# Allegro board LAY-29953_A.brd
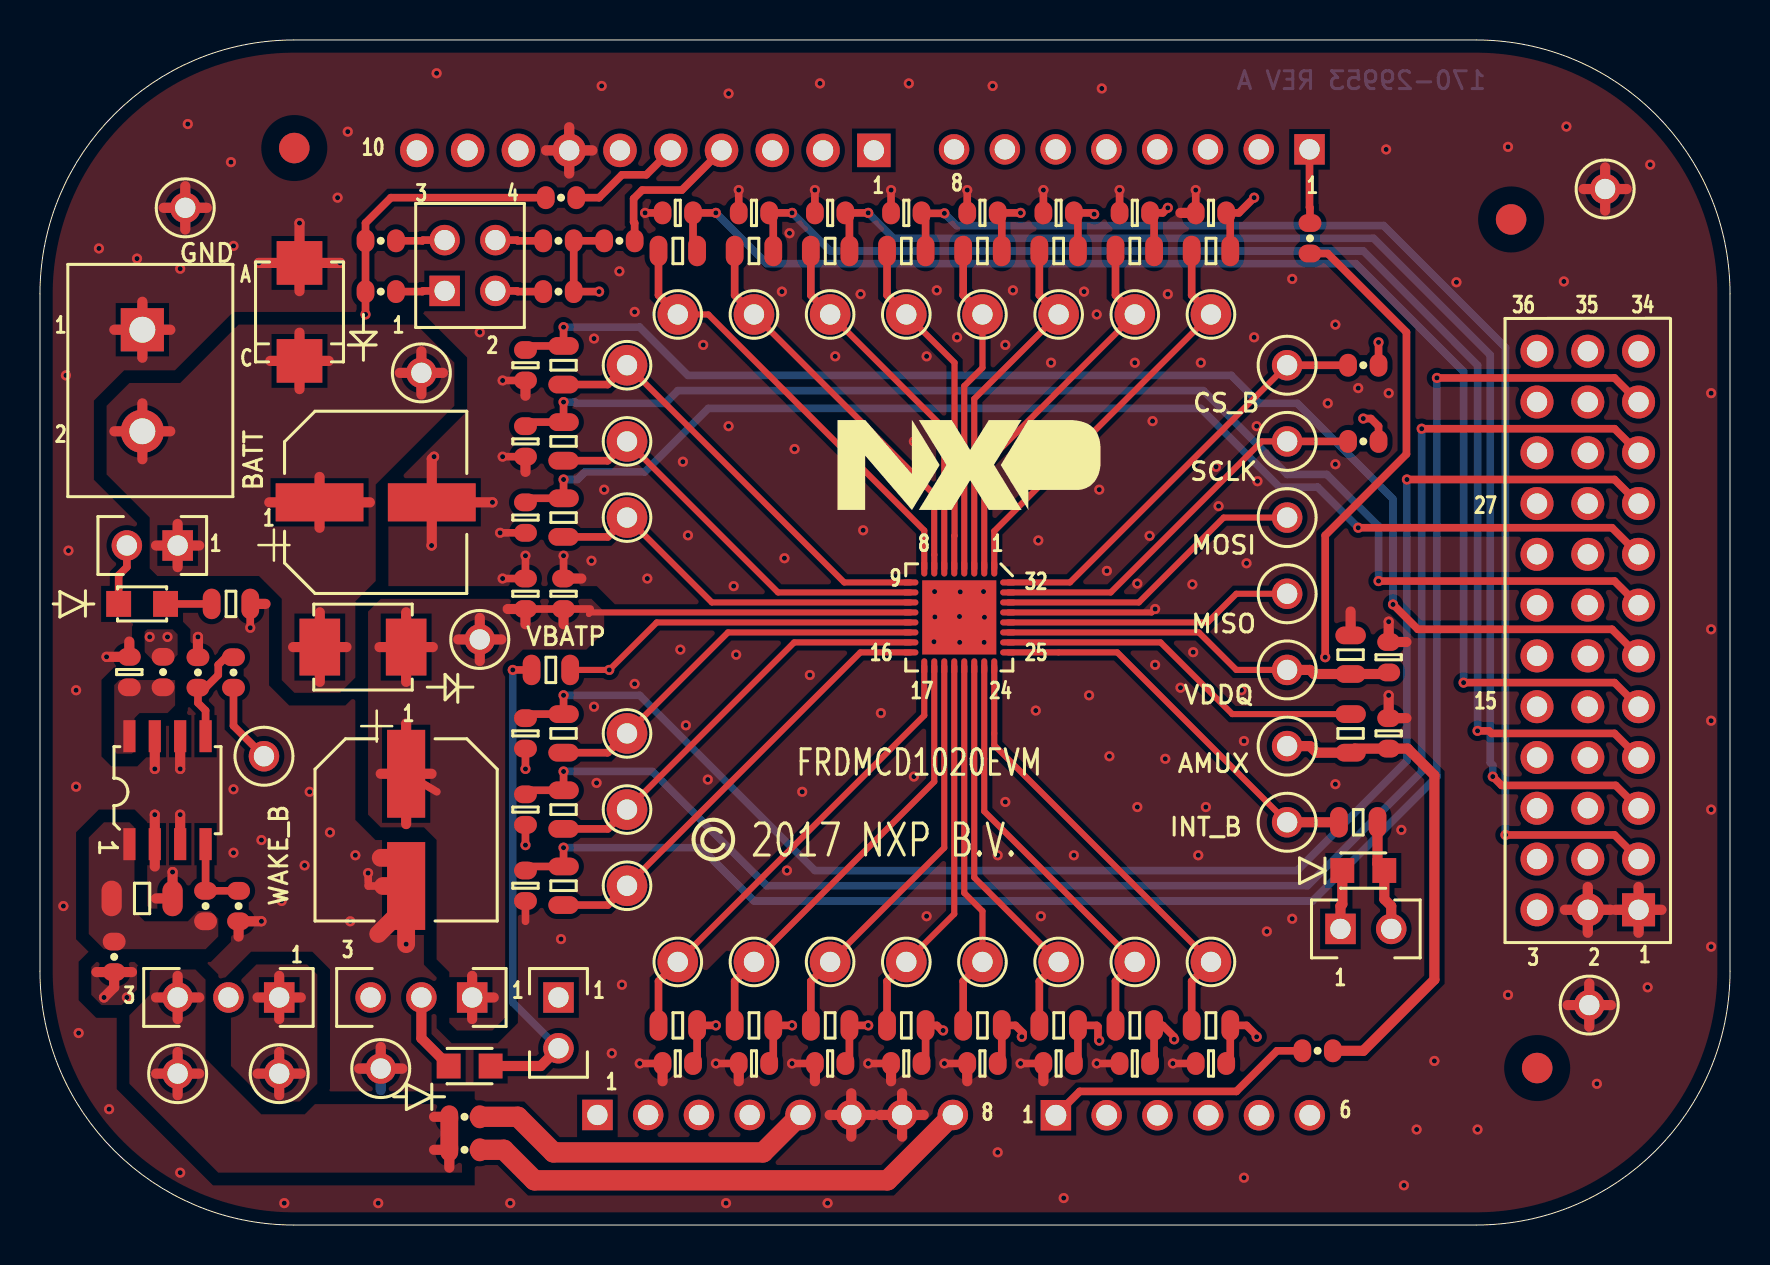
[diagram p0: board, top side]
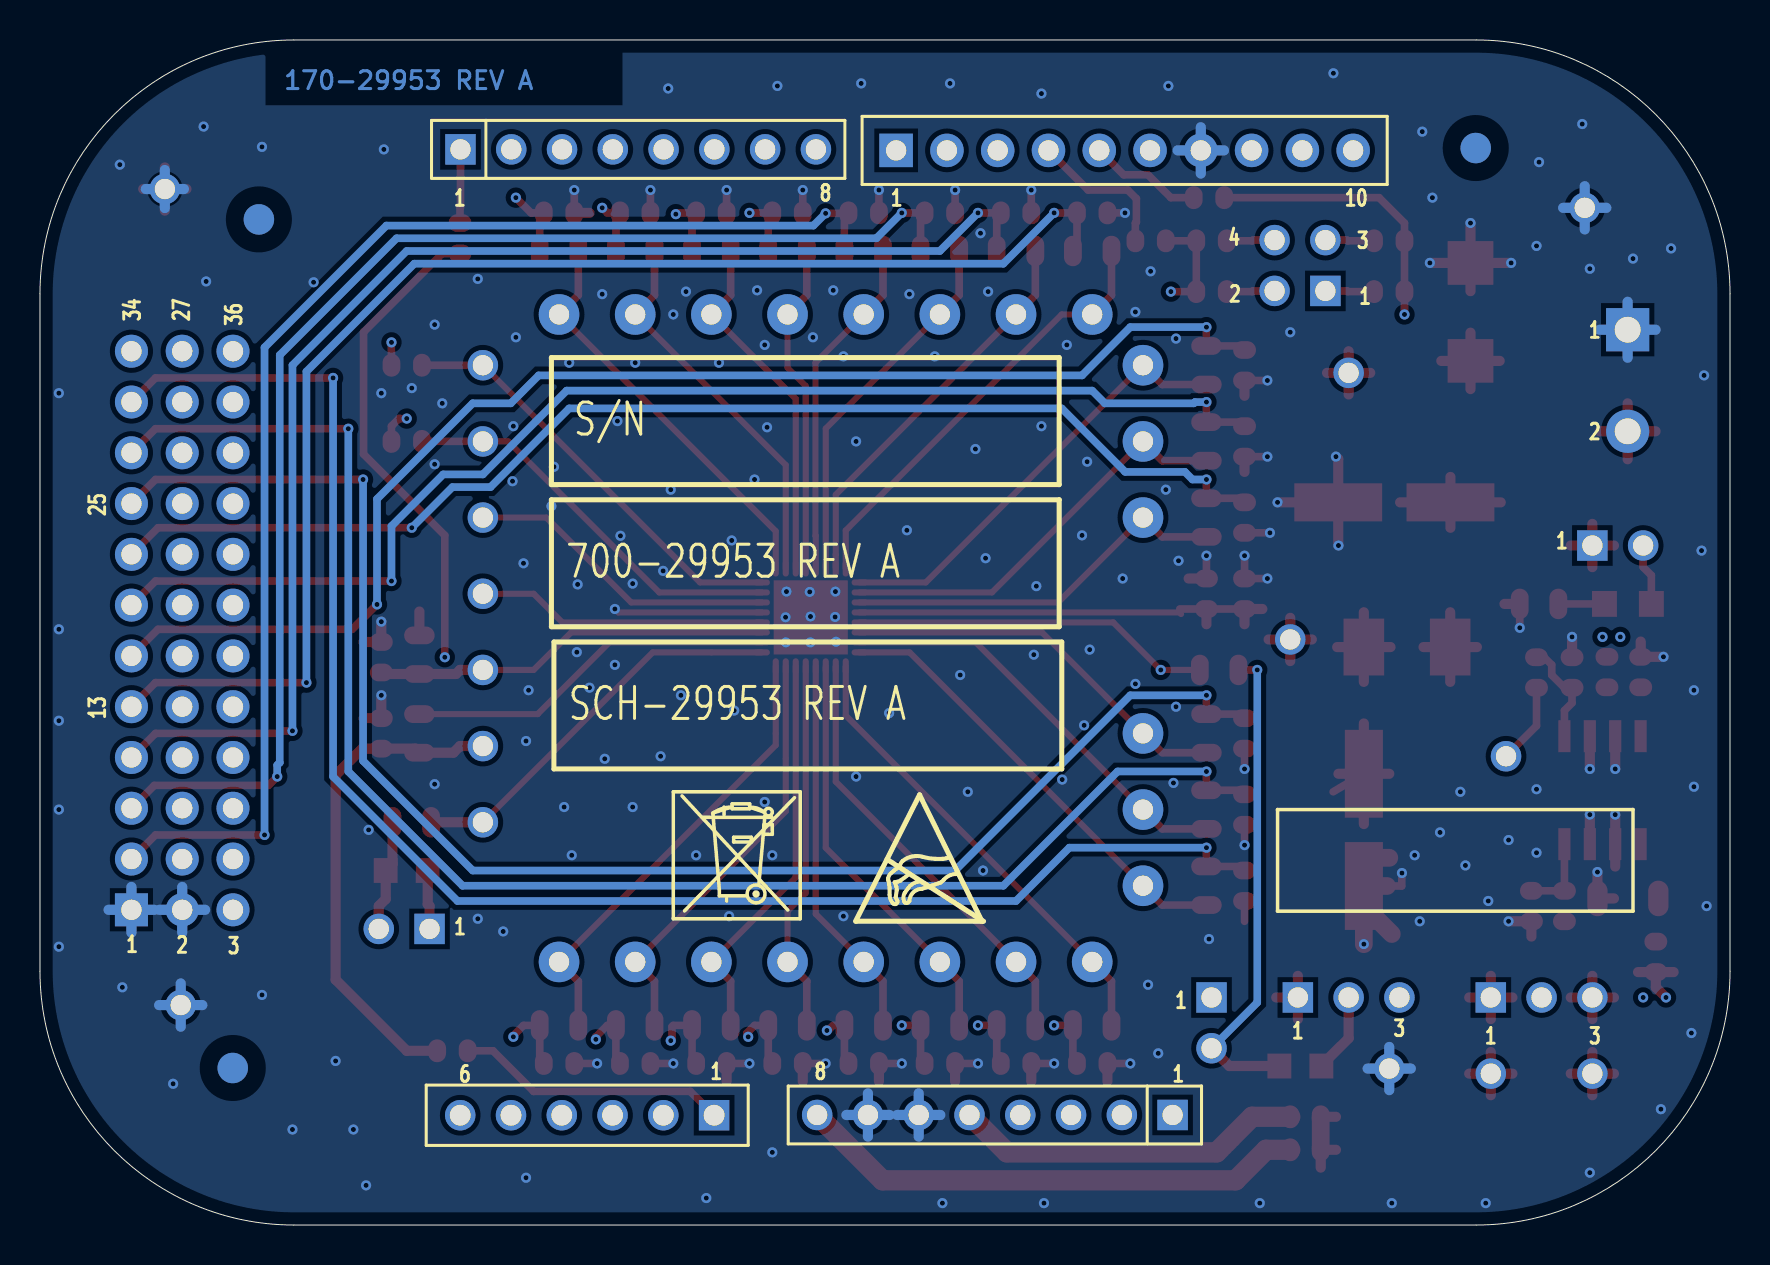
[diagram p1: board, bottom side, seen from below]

Outline 84.54 x 59.27 mm; copper layers: TOP, INNER_1, INNER_2, BOTTOM. Coordinates in mm from the lower left corner of the outline.
Outline path: 0,46.57 arc(3.72,55.55) 12.7,59.27 71.84,59.27 arc(80.82,55.55) 84.54,46.57 84.54,12.7 arc(80.82,3.72) 71.84,0 12.7,0 arc(3.72,3.72) 0,12.7 0,46.57

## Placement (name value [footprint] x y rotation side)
BATT1  TEST POINT RED  [TEST_LOOP]  19.08 42.62 0 top
C1  0.1uF  [CC0603_OV]  43.33 50.62 180 top
C2  0.1uF  [CC0603_OV]  39.52 50.62 180 top
C3  0.1uF  [CC0603_OV]  35.71 50.62 180 top
C4  0.1uF  [CC0603_OV]  31.9 50.62 180 top
C5  0.1uF  [CC0603_OV]  24.28 43 270 top
C6  0.1uF  [CC0603_OV]  24.28 39.19 270 top
C7  0.1uF  [CC0603_OV]  24.28 35.38 270 top
C8  0.1uF  [CC0603_OV]  24.28 24.59 270 top
C9  0.1uF  [CC0603_OV]  24.28 20.78 270 top
C10  0.1uF  [CC0603_OV]  24.28 16.97 270 top
C11  0.1uF  [CC0603_OV]  31.9 8.08 180 top
C12  0.1uF  [CC0603_OV]  35.71 8.08 180 top
C13  0.1uF  [CC0603_OV]  39.52 8.08 180 top
C14  0.1uF  [CC0603_OV]  43.33 8.08 180 top
C22  100uF  [CCE8P3X8P3]  18.32 19.76 270 top
C23  1000PF  [CC0603_OV]  67.46 24.59 90 top
C24  0.1uF  [CC0603_OV]  26.19 31.57 90 top
C25  1000PF  [CC0603_OV]  24.28 31.57 90 top
C26  0.1uF  [CC0603_OV]  67.46 28.4 90 top
C31  0.1uF  [CC0603_OV]  58.57 8.08 180 top
C32  0.1uF  [CC0603_OV]  54.76 8.08 180 top
C33  0.1uF  [CC0603_OV]  50.95 8.08 180 top
C34  0.1uF  [CC0603_OV]  47.14 8.08 180 top
C35  0.1uF  [CC0603_OV]  47.14 50.62 180 top
C36  0.1uF  [CC0603_OV]  50.95 50.62 180 top
C37  0.1uF  [CC0603_OV]  54.76 50.62 180 top
C38  0.1uF  [CC0603_OV]  58.57 50.62 180 top
C39  0.1UF  [CC0603_OV]  4.47 27.66 90 top
C40  10uF  [CC1206_OV]  5.11 16.33 0 top
C41  10uF  [CC0805_OV]  65.56 28.53 90 top
C42  100uF  [CCE8P3X8P3]  16.79 36.15 0 top
D1  ES3AB-13-F  [SMB_4P57X3P94MM]  16.16 28.91 180 top
D2  RED  [LED_2P_0805]  21.49 7.95 180 top
D3  RED  [LED_2P_0805]  66.19 17.73 180 top
D4  SMBJ40  [DO-214AA_A]  12.98 45.67 90 top
D5  GREEN  [LED2_2P34_2P1X1P25]  5.11 31.07 180 top
GND1  TEST POINT BLACK  [TEST_LOOP]  7.27 50.88 0 top
GND2  TEST POINT BLACK  [TEST_LOOP]  17.05 7.83 0 top
GND3  TEST POINT BLACK  [TEST_LOOP]  78.29 51.82 0 top
GND4  TEST POINT BLACK  [TEST_LOOP]  77.5 11 0 top
J1  HDR 1X10  [HDR110]  41.71 53.75 90 bottom
J2  HDR_1X8  [JUMP1X8-6040]  63.51 53.8 90 bottom
J3  HDR 1X2  [HDR102]  65.05 14.81 90 top
J4  HDR 1X2  [HDR102]  6.89 33.99 270 top
J5  OSTTC022162  [CON2_TB_5P08_TH_OSTTC]  5.12 44.78 270 top
J6  HDR_1X3  [HDR103]  21.62 11.38 270 top
J7  HDR 1X2  [HDR102]  25.94 11.38 0 top
J8  HDR_1X8  [JUMP1X8-6040]  27.88 5.5 270 bottom
J9  HDR 1X6  [HDR106_TH_TSW]  50.82 5.49 270 bottom
J14  HDR_1X3  [HDR103]  11.97 11.38 270 top
J16  HDR_3X12  [HDR_3X12_100_TH]  79.96 15.77 90 top
J17  SKT_2X2  [SKT2X2_TH_SSQ]  20.24 46.72 180 top
NOREF  -  []  29.13 39.23 90 top
NOREF#2  -  []  43.48 27.89 90 top
NOREF#3  -  []  230.3 -47.15 0 top
NOREF#4  -  []  44.23 27.94 0 top
NOREF#5  -  []  43.48 27.89 90 top
NOREF#6  -  []  33.68 19.26 0 top
NOREF#7  -  []  0 46.57 0 top
NOREF#8  -  []  47.73 27.94 90 top
NOREF#9  -  []  43.53 28.64 0 top
NOREF#10  -  []  -16.61 -33.78 0 top
NOREF#11  -  [unnamed#2]  74.89 7.85 0 top
NOREF#12  -  [unnamed#2]  12.72 53.87 0 top
NOREF#13  -  []  48.48 32.38 90 top
NOREF#14  -  []  47.73 27.94 90 top
NOREF#15  -  []  230.3 -73.82 90 top
NOREF#16  -  []  48.48 27.89 0 top
NOREF#17  -  []  -408.02 -336.95 0 top
NOREF#18  -  []  6.89 7.57 0 top
NOREF#19  -  []  43.53 28.64 0 top
NOREF#20  -  []  20.24 46.72 90 top
NOREF#21  -  []  39.17 53.75 0 top
NOREF#22  -  [unnamed#2]  73.59 50.3 0 top
NOREF#23  -  []  48.48 32.38 90 top
NOREF#24  -  []  43.53 31.64 90 top
NOREF#25  -  []  48.43 28.64 90 top
NOREF#26  -  []  71.84 0 90 top
NOREF#27  -  []  48.43 28.64 90 top
NOREF#28  -  []  4.85 20.78 0 top
NOREF#29  -  []  43.53 31.64 90 top
NOREF#30  -  []  5.04 56.7 0 top
NOREF#31  -  []  44.23 32.84 0 top
NOREF#32  -  []  44.23 27.94 0 top
NOREF#33  -  []  -381.99 188.19 0 top
NOREF#34  -  []  39.91 35.77 0 top
NOREF#35  -  []  43.72 15.19 180 bottom
NOREF#36  -  []  58.83 22.81 180 bottom
NOREF#37  -  [unnamed#2]  12.72 53.87 180 bottom
NOREF#38  -  []  91.8 42.45 180 bottom
NOREF#39  -  []  4.85 20.78 0 bottom
NOREF#40  -  [unnamed#2]  74.9 7.85 180 bottom
NOREF#41  -  []  52.86 15.32 180 bottom
NOREF#42  -  [unnamed#2]  73.59 50.3 180 bottom
NOREF#43  -  []  58.96 29.92 180 bottom
NOREF#44  -  []  33.56 43.39 0 bottom
R1  100  [RC0805_OV]  43.33 48.72 180 top
R2  100  [RC0805_OV]  39.52 48.72 180 top
R3  100  [RC0805_OV]  35.71 48.72 180 top
R4  100  [RC0805_OV]  31.9 48.72 180 top
R5  100  [RC0805_OV]  26.19 43 270 top
R6  100  [RC0805_OV]  26.19 39.19 270 top
R7  100  [RC0805_OV]  26.19 35.38 270 top
R8  100  [RC0805_OV]  26.19 24.59 270 top
R9  100  [RC0805_OV]  26.19 20.78 270 top
R10  100  [RC0805_OV]  26.19 16.97 270 top
R11  100  [RC0805_OV]  31.9 9.98 180 top
R12  100  [RC0805_OV]  35.71 9.98 180 top
R13  100  [RC0805_OV]  39.52 9.98 180 top
R14  100  [RC0805_OV]  43.33 9.98 180 top
R22  1K  [RC0805_OV]  65.56 24.59 90 top
R23  10K  [RC0805_OV]  65.94 20.14 0 top
R24  100  [RC0805_OV]  58.57 48.72 0 top
R25  100  [RC0805_OV]  54.76 48.72 0 top
R26  100  [RC0805_OV]  50.95 48.72 0 top
R27  100  [RC0805_OV]  47.14 48.72 0 top
R28  100  [RC0805_OV]  47.14 9.98 0 top
R29  100  [RC0805_OV]  50.95 9.98 0 top
R30  100  [RC0805_OV]  54.76 9.98 0 top
R31  100  [RC0805_OV]  58.57 9.98 0 top
R36  10K  [RC0805_OV]  25.55 27.76 180 top
R37  0  [RC0603_OV]  66.19 43 0 top
R38  0  [RC0603_OV]  66.19 39.19 0 top
R39  0  [RC0603_OV]  26.06 51.39 0 top
R40  0  [RC0603_OV]  28.98 49.23 0 top
R41  0  [RC0603_OV]  63.53 49.35 90 top
R42  0  [RC0603_OV]  3.71 13.41 270 top
R43  0  [RC0603_OV]  6.16 27.66 270 top
R44  10K  [RC0805_OV]  9.55 31.07 180 top
R45  0  [RC0603_OV]  21.24 5.41 0 top
R46  0  [RC0603_OV]  21.24 3.76 0 top
R47  0  [RC0603_OV]  63.91 8.71 180 top
R48  0  [RC0603_OV]  17.05 46.69 180 top
R49  0  [RC0603_OV]  17.05 49.23 180 top
R50  0  [RC0603_OV]  25.94 46.69 180 top
R51  0  [RC0603_OV]  25.94 49.23 180 top
R61  47K  [RC0603_OV]  8.28 15.95 270 top
R62  150.0K  [RC0603_OV]  9.93 15.95 270 top
R63  0  [RC0603_OV]  7.9 27.64 270 top
R64  0  [RC0603_OV]  9.68 27.64 90 top
SG0  TH  [MST_TESTPOINT]  43.33 45.54 0 top
SG1  TH  [MST_TESTPOINT]  39.52 45.54 0 top
SG2  TH  [MST_TESTPOINT]  35.71 45.54 0 top
SG3  TH  [MST_TESTPOINT]  31.9 45.54 0 top
SG4  TH  [MST_TESTPOINT]  29.36 43 90 top
SG5  TH  [MST_TESTPOINT]  29.36 39.19 90 top
SG6  TH  [MST_TESTPOINT]  29.36 35.38 90 top
SG7  TH  [MST_TESTPOINT]  29.36 24.59 90 top
SG8  TH  [MST_TESTPOINT]  29.36 20.78 90 top
SG9  TH  [MST_TESTPOINT]  29.36 16.97 0 top
SG10  TH  [MST_TESTPOINT]  31.9 13.16 90 top
SG11  TH  [MST_TESTPOINT]  35.71 13.16 90 top
SG12  TH  [MST_TESTPOINT]  39.52 13.16 90 top
SG13  TH  [MST_TESTPOINT]  43.33 13.16 90 top
SP0  TH  [MST_TESTPOINT]  58.57 45.54 90 top
SP1  TH  [MST_TESTPOINT]  54.76 45.54 90 top
SP2  TH  [MST_TESTPOINT]  50.95 45.54 90 top
SP3  TH  [MST_TESTPOINT]  47.14 45.54 90 top
SP4  TH  [MST_TESTPOINT]  47.14 13.16 180 top
SP5  TH  [MST_TESTPOINT]  50.95 13.16 0 top
SP6  TH  [MST_TESTPOINT]  54.76 13.16 0 top
SP7  TH  [MST_TESTPOINT]  58.57 13.16 0 top
TP1  TEST POINT RED  [TEST_LOOP]  22 29.29 0 top
TP2  TEST POINT RED  [TEST_LOOP]  62.38 27.76 0 top
TP3  TEST POINT RED  [TEST_LOOP]  62.38 39.19 0 top
TP4  TEST POINT RED  [TEST_LOOP]  62.38 31.57 0 top
TP5  TEST POINT RED  [TEST_LOOP]  62.38 35.38 0 top
TP6  TEST POINT RED  [TEST_LOOP]  62.38 43 0 top
TP7  TEST POINT RED  [TEST_LOOP]  62.38 20.14 0 top
TP8  TEST POINT RED  [TEST_LOOP]  11.2 23.45 0 top
TP9  TEST POINT RED  [TEST_LOOP]  62.38 23.95 0 top
U2  LM2931CDG  [SO8_1P27_4X5]  6.38 21.75 90 top
U3  PC33CD1020AES  [QFN32_0P5_5X5_S146EP]  45.98 30.39 270 top
UNK3V3  TEST POINT RED  [TEST_LOOP]  11.97 7.57 0 top
UNK5V0  TEST POINT RED  [TEST_LOOP]  6.89 7.57 0 top

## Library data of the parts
BATT1 GND1-GND4 TP1-TP9 UNK3V3 UNK5V0 = TestLoop
C1-C14 C23-C26 C31-C41 = CAP_NP
C22 C42 = CAP_POL
D1 = DIODE
D2 D3 D5 = LED
D4 = DIODE_TVS
J1 = HDR-1X10
J2 J8 = HDR-1X8
J3-J5 J7 = CONN_HDR_2X1
J6 J14 = CONN_HDR_3X1
J9 = CONN_HDR_6X1
J16 = HDR-3X12
J17 = CONN_HDR_2X2
R1-R14 R22-R31 R36-R51 R61-R64 = RES
SG0-SG13 SP0-SP7 = T POINT S
U2 = LM2931_SO8
U3 = PC33978_QFN32

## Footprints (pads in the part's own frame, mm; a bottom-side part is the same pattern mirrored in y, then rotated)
CC0603_OV
  oval 0.889x1.143 smd: 1(-0.762,0) 2(0.762,0)
CC0805_OV
  oval 0.889x1.524 smd: 1(-0.965,0) 2(0.965,0)
CC1206_OV
  oval 1.016x1.778 smd: 1(-1.524,0) 2(1.524,0)
CCE8P3X8P3
  rect 4.394x1.905 smd: 1(-2.807,0) 2(2.807,0)
CON2_TB_5P08_TH_OSTTC
  rect 2.159x2.159 hole 1.295: 1(0,0)
  round 2.159 hole 1.295: 2(5.08,0)
DO-214AA_A
  rect 2.184x2.286 smd: A(2.45,0) C(-2.45,0)
HDR102
  rect 1.524x1.524 hole 1.016: 1(0,0)
  round 1.524 hole 1.016: 2(0,-2.54)
HDR103
  rect 1.524x1.524 hole 1.016: 1(0,0)
  round 1.524 hole 1.016: 2(0,-2.54) 3(0,-5.08)
HDR106_TH_TSW
  rect 1.524x1.524 hole 1.041: 1(0,0)
  round 1.524 hole 1.041: 2(0,-2.54) 3(0,-5.08) 4(0,-7.62) 5(0,-10.16) 6(0,-12.7)
HDR110
  rect 1.676x1.676 hole 1.016: 1(0,0)
  round 1.676 hole 1.016: 2(0,-2.54) 3(0,-5.08) 4(0,-7.62) 5(0,-10.16) 6(0,-12.7) 7(0,-15.24) 8(0,-17.78) 9(0,-20.32) 10(0,-22.86)
HDR_3X12_100_TH
  rect 1.651x1.651 hole 1.016: 1(0,0)
  round 1.651 hole 1.016: 2(0,2.54) 3(0,5.08) 4(2.54,0) 5(2.54,2.54) 6(2.54,5.08) 7(5.08,0) 8(5.08,2.54) 9(5.08,5.08) 10(7.62,0) 11(7.62,2.54) 12(7.62,5.08) 13(10.16,0) 14(10.16,2.54) 15(10.16,5.08) 16(12.7,0) 17(12.7,2.54) 18(12.7,5.08) 19(15.24,0) 20(15.24,2.54) 21(15.24,5.08) 22(17.78,0) 23(17.78,2.54) 24(17.78,5.08) 25(20.32,0) 26(20.32,2.54) 27(20.32,5.08) 28(22.86,0) 29(22.86,2.54) 30(22.86,5.08) 31(25.4,0) 32(25.4,2.54) 33(25.4,5.08) 34(27.94,0) 35(27.94,2.54) 36(27.94,5.08)
JUMP1X8-6040
  rect 1.524x1.524 hole 1.016: 1(0,0)
  round 1.524 hole 1.016: 2(0,-2.54) 3(0,-5.08) 4(0,-7.62) 5(0,-10.16) 6(0,-12.7) 7(0,-15.24) 8(0,-17.78)
LED2_2P34_2P1X1P25
  rect 1.245x1.295 smd: A(1.172,0) C(-1.172,0)
LED_2P_0805
  rect 1.194x1.245 smd: A(1.05,0) C(-1.05,0)
MST_TESTPOINT
  round 2.032 hole 1.016: 1(0,0)
QFN32_0P5_5X5_S146EP
  oval 0.813x0.305 smd: 1(-2.45,1.75) 2(-2.45,1.25) 3(-2.45,0.75) 4(-2.45,0.25) 5(-2.45,-0.25) 6(-2.45,-0.75) 7(-2.45,-1.25) 8(-2.45,-1.75) 17(2.45,-1.75) 18(2.45,-1.25) 19(2.45,-0.75) 20(2.45,-0.25) 21(2.45,0.25) 22(2.45,0.75) 23(2.45,1.25) 24(2.45,1.75)
  oval 0.305x0.813 smd: 9(-1.75,-2.45) 10(-1.25,-2.45) 11(-0.75,-2.45) 12(-0.25,-2.45) 13(0.25,-2.45) 14(0.75,-2.45) 15(1.25,-2.45) 16(1.75,-2.45) 25(1.75,2.45) 26(1.25,2.45) 27(0.75,2.45) 28(0.25,2.45) 29(-0.25,2.45) 30(-0.75,2.45) 31(-1.25,2.45) 32(-1.75,2.45)
  rect 3.708x3.708 smd: 33(0,0)
RC0603_OV
  oval 0.889x1.143 smd: 1(-0.762,0) 2(0.762,0)
RC0805_OV
  oval 0.889x1.524 smd: 1(-0.965,0) 2(0.965,0)
SKT2X2_TH_SSQ
  rect 1.524x1.524 hole 1.016: 1(0,0)
  round 1.524 hole 1.016: 2(-2.54,0) 3(0,-2.54) 4(-2.54,-2.54)
SMB_4P57X3P94MM
  rect 2.032x2.845 smd: A(2.16,0) C(-2.16,0)
SO8_1P27_4X5
  rect 1.6x0.61 smd: 1(-2.7,1.905) 2(-2.7,0.635) 3(-2.7,-0.635) 4(-2.7,-1.905) 5(2.7,-1.905) 6(2.7,-0.635) 7(2.7,0.635) 8(2.7,1.905)
TEST_LOOP
  round 1.524 hole 1.016: 1(0,0)
unnamed#2
  round 1.524 smd: (0,0)

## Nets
3V3_MCU: J8.4 J14.1 UNK3V3.1
5V0_MCU: J14.3 R45.1 R46.1 UNK5V0.1
VBATP: C22.1 C24.1 C25.1 D1.C(CATHODE) J6.1 R43.1 TP1.1(PIN1) U3.12(VBATP)
VDDQ: C26.1 C41.1 D3.A(ANODE) J3.1 J6.3 J14.2 R42.2 TP2.1(PIN1) U3.27(VDDQ)
0: C1.2 C2.2 C3.2 C4.2 C5.2 C6.2 C7.2 C8.2 C9.2 C10.2 C11.2 C12.2 C13.2 C14.2 C22.2 C23.2 C24.2 C25.2 C26.2 C31.2 C32.2 C33.2 C34.2 C35.2 C36.2 C37.2 C38.2 C39.2 C40.2 C41.2 C42.2 D4.A GND1.1(PIN1) GND2.1(PIN1) GND3.1(PIN1) GND4.1(PIN1) J1.7 J5.1 J8.6 J8.7 J16.1 J16.2 R44.1 R62.2 R63.1 U2.2(GND1) U2.3(GND2) U2.6(GND3) U2.7(GND4) U3.29(GND) U3.33(EP_GND)
AMUX: C23.1 R22.1 R47.1 TP9.1(PIN1)
BATTERY: BATT1.1(PIN1) C42.1 D1.A(ANODE) D4.C J4.1 J5.2 J16.35
CS_B: R37.1 TP6.1(PIN1) U3.32(C\S\)
CSB_M: J1.3 R37.2
INT_B: R23.1 R41.1 TP7.1(PIN1) U3.25(I\N\T\)
INTB_M: J2.1 R41.2
MISO: R39.1 R48.2 R49.2 TP4.1(PIN1) U3.28(MISO)
MISO_M: J1.5 R39.2
MOSI: R40.1 R50.1 R51.1 TP5.1(PIN1) U3.30(MOSI)
MOSI_M: J1.4 R40.2
OUT: C40.1 R42.1 R61.2 U2.1(OUT)
SCLK: R38.1 TP3.1(PIN1) U3.31(SCLK)
SCLK_M: J1.6 R38.2
SG0: R1.2 SG0.1(TP) U3.5(SG0)
SG0R: C1.1 J16.4 R1.1
SG1: R2.2 SG1.1(TP) U3.6(SG1)
SG1R: C2.1 J16.7 R2.1
SG2: R3.2 SG2.1(TP) U3.7(SG2)
SG2R: C3.1 J16.10 R3.1
SG3: R4.2 SG3.1(TP) U3.8(SG3)
SG3R: C4.1 J16.13 R4.1
SG4: R5.2 SG4.1(TP) U3.9(SG4)
SG4R: C5.1 J16.16 R5.1
SG5: R6.2 SG5.1(TP) U3.10(SG5)
SG5R: C6.1 J16.19 R6.1
SG6: R7.2 SG6.1(TP) U3.11(SG6)
SG6R: C7.1 J16.22 R7.1
SG7: R8.2 SG7.1(TP) U3.14(SG7)
SG7R: C8.1 J16.25 R8.1
SG8: R9.2 SG8.1(TP) U3.15(SG8)
SG8R: C9.1 J16.28 R9.1
SG9: R10.2 SG9.1(TP) U3.16(SG9)
SG9R: C10.1 J16.31 R10.1
SG10: R11.2 SG10.1(TP) U3.17(SG10)
SG10R: C11.1 J16.34 R11.1
SG11: R12.2 SG11.1(TP) U3.18(SG11)
SG11R: C12.1 J16.32 R12.1
SG12: R13.2 SG12.1(TP) U3.19(SG12)
SG12R: C13.1 J16.29 R13.1
SG13: R14.2 SG13.1(TP) U3.20(SG13)
SG13R: C14.1 J16.26 R14.1
SP0: R24.1 SP0.1(TP) U3.1(SP0)
SP0R: C38.1 J16.3 R24.2
SP1: R25.1 SP1.1(TP) U3.2(SP1)
SP1R: C37.1 J16.6 R25.2
SP2: R26.1 SP2.1(TP) U3.3(SP2)
SP2R: C36.1 J16.9 R26.2
SP3: R27.1 SP3.1(TP) U3.4(SP3)
SP3R: C35.1 J16.12 R27.2
SP4: R28.1 SP4.1(TP) U3.21(SP4)
SP4R: C34.1 J16.15 R28.2
SP5: R29.1 SP5.1(TP) U3.22(SP5)
SP5R: C33.1 J16.18 R29.2
SP6: R30.1 SP6.1(TP) U3.23(SP6)
SP6R: C32.1 J16.21 R30.2
SP7: R31.1 SP7.1(TP) U3.24(SP7)
SP7R: C31.1 J16.24 R31.2
WAKE_B: R36.1 R64.1 TP8.1(PIN1) U3.13(W\A\K\E\)
N46347: R22.2 U3.26(AMUX)
N63980: D2.A(ANODE) J6.2 J7.1
N64526: D2.C(CATHODE) J7.2 R36.2
N74267: D3.C(CATHODE) J3.2 R23.2
N81888: D5.A(ANODE) J4.2
N159644: J8.5 R45.2
N159652: J8.8 R46.2
N165115: J9.1 R47.2
N222829: C39.1 R43.2 U2.8(IN)
N224295: R61.1 R62.1 U2.4(ADJ)
N235544: R63.2 R64.2 U2.5(OUT_INH)
N794881: D5.C(CATHODE) R44.2
N1652660: J17.1(A1) R48.1
N1652840: J17.3(A2) R49.1
N1653021: J17.2(B1) R50.2
N1653201: J17.4(B2) R51.2

Pads without a net: J1 1 2 8 9 10; J2 2 3 4 5 6 7 8; J8 1 2 3; J9 2 3 4 5 6; J16 5 8 11 14 17 20 23 27 30 33 36

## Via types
v1: diameter 0.508, hole 0.254, TOP to BOTTOM, 242 vias

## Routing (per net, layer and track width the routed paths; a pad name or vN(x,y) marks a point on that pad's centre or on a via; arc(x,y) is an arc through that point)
3V3_MCU: length 17.3
  TOP w0.508: UNK3V3.1 13.05,7.57 ; UNK3V3.1 11.97,6.49 ; UNK3V3.1 11.97,8.65 ; UNK3V3.1 10.89,7.57 ; 11.97,10.3 J14.1 ; J14.1 13.05,11.38 ; J14.1 11.97,12.46 ; J14.1 10.89,11.38
  INNER_2 w0.508: J8.4 35.5,6.58 ; J8.4 36.58,5.5 ; J8.4 35.5,4.42 ; J8.4 34.42,5.5 ; UNK3V3.1 11.97,8.65 ; UNK3V3.1 10.89,7.57 ; UNK3V3.1 11.97,6.49 ; UNK3V3.1 13.05,7.57
5V0_MCU: length 12.7
  TOP w0.508: UNK5V0.1 6.89,8.65 ; UNK5V0.1 6.89,6.49 ; UNK5V0.1 7.97,7.57 ; UNK5V0.1 5.81,7.57 ; 6.89,10.3 J14.3 ; J14.3 6.89,12.46 ; J14.3 7.97,11.38 ; J14.3 5.81,11.38 ; 20.47,2.87 R46.1 19.71,3.76 ; 19.71,5.41 R45.1
  TOP w0.889: R46.1 R45.1
VBATP: length 49.1
  TOP w0.305: U3.12 27.54,30.64 27.46,30.56
  TOP w0.381: C22.1 19.85,21.67 ; 27.52,30.81 C24.1 C25.1
  TOP w0.508: J6.1 22.7,11.38 ; J6.1 21.62,10.3 ; J6.1 21.62,12.46 ; C22.1 19.59,22.57 ; C22.1 18.32,20.06 ; C22.1 18.32,25.09 ; C22.1 17.05,22.57 ; D1.C 19.65,28.91 ; D1.C 18.32,30.65 ; D1.C 16.98,28.91 ; D1.C 18.32,27.17 ; 23.4,30.81 C25.1 24.28,30.05 ; 22,28.21 TP1.1 ; TP1.1 20.92,29.29 ; TP1.1 22,30.37 ; TP1.1 23.08,29.29 ; 26.19,30.05 C24.1
  INNER_2 w0.508: TP1.1 22,30.37 ; TP1.1 23.08,29.29 ; TP1.1 20.92,29.29 ; TP1.1 22,28.21
  vias: v1(5.49,29.42) v1(6.38,29.42)
VDDQ: length 41.3
  TOP w0.305: U3.27 57.97,29.64 59.84,27.76 TP2.1
  TOP w0.508: v1(3.2,11.38) 3.71,11.89 R42.2 ; 2.82,12.65 R42.2 ; R42.2 4.6,12.65 ; D3.A 65.14,16.05 65.05,15.95 J3.1 ; TP2.1 63.53,27.76 63.73,27.56 C41.1 67.39,27.56 C26.1
  INNER_2 w0.508: 61.3,27.76 TP2.1 ; TP2.1 62.38,26.68 ; TP2.1 63.46,27.76 ; J14.2 10.51,11.38 ; J14.2 9.43,12.46 ; J14.2 8.35,11.38 ; J14.2 9.43,10.3 ; J6.3 17.62,11.38 ; J6.3 16.54,10.3 ; J6.3 15.46,11.38 ; J6.3 16.54,12.46 ; J3.1 65.05,15.89 ; J3.1 65.05,13.73 ; J3.1 63.97,14.81
  vias: v1(4.35,11.38)
0: length 312.8
  TOP w0.305: U3.29 55.61,30.64 v1(55.78,30.81)
  TOP w0.381: v1(45.24,8.08) C34.2 ; v1(30.27,50.62) C4.2 ; v1(23.01,34.62) C7.2 ; v1(23.14,38.43) C6.2 ; v1(46.38,51.77) C35.2 ; R44.1 v1(10.52,29.87) ; 17.16,16.96 16.42,16.96 v1(16.41,17.6) ; 24.28,15.19 C10.2 ; v1(24.28,22.81) C8.2 ; C14.2 v1(41.43,8.08) ; v1(23.14,32.34) C25.2 v1(24.28,33.48) ; v1(50.19,51.77) C36.2 ; C12.2 v1(33.81,8.08) ; C11.2 v1(30,8.08) ; C31.2 v1(56.67,8.08) ; v1(38.76,51.77) 38.76,50.62 ; v1(49.05,8.08) C33.2 ; v1(26.19,33.48) C24.2 ; v1(24.28,19) C9.2 ; v1(23.14,42.24) C5.2 ; 38.76,8.08 v1(37.62,8.08) ; v1(34.95,51.77) C3.2 ; v1(57.81,51.77) C38.2 ; v1(52.86,8.08) C32.2 ; v1(54,51.77) C37.2 ; v1(42.57,51.77) C1.2
  TOP w0.508: J16.1 79.96,16.91 ; J16.1 78.82,15.77 ; J16.1 81.11,15.77 ; J16.1 79.96,14.62 ; J16.2 78.57,15.77 ; J16.2 77.42,14.62 ; J16.2 76.28,15.77 ; J16.2 77.42,16.91 ; J5.1 5.12,46.18 ; J5.1 5.12,43.38 ; J5.1 3.72,44.78 ; J5.1 6.52,44.78 ; GND2.1 17.05,8.91 ; GND2.1 15.97,7.83 ; GND2.1 18.13,7.83 ; v1(67.46,26.49) C23.2 68.35,25.35 ; 34.95,7.19 C12.2 ; 77.21,51.82 GND3.1 ; GND3.1 78.29,50.74 ; GND3.1 78.29,52.9 ; GND3.1 79.37,51.82 ; v1(19.71,38.43) 19.6,38.32 C42.2 ; 12.98,46.71 D4.A ; D4.A v1(12.98,50.12) ; D4.A v1(10.95,48.12) ; D4.A v1(15.01,48.12) ; 6.19,50.88 GND1.1 ; GND1.1 7.27,51.96 ; GND1.1 7.27,49.8 ; GND1.1 8.35,50.88 ; 5.74,24.45 v1(5.74,22.81) ; J8.6 40.58,6.58 ; J8.6 41.66,5.5 ; J8.6 40.58,4.42 ; J8.6 39.5,5.5 ; 43.12,4.42 J8.7 ; J8.7 44.2,5.5 ; J8.7 43.12,6.58 ; J8.7 42.04,5.5 ; 76.42,11 GND4.1 ; GND4.1 77.5,9.92 ; GND4.1 77.5,12.08 ; GND4.1 78.58,11 ; C24.2 27.08,32.34 ; C42.2 19.6,34 v1(19.59,33.99) ; C42.2 v1(22.63,36.15) ; 68.35,29.16 C26.2 v1(67.46,30.18) ; J1.7 26.47,54.91 ; J1.7 25.32,53.75 ; J1.7 27.63,53.75 ; J1.7 26.47,52.6 ; 4.47,29.18 C39.2 v1(3.33,28.42) ; 5.81,16.33 C40.2 v1(6.63,17.66) ; 9.93,14.43 R62.2 v1(11.08,15.19) ; 31.14,7.19 C11.2 ; 24.28,41.48 C5.2 ; 5.74,17.93 U2.2 v1(5.74,20.53) ; 50.19,7.19 C33.2 ; 24.28,37.67 C6.2 ; R63.1 v1(7.9,29.42) ; 46.38,7.19 C34.2 ; 42.57,7.19 C14.2 ; 57.05,50.62 C38.2 ; C41.2 65.56,30.69 ; R44.1 11.28,31.07 ; 7.01,19.05 v1(7.01,20.53) ; 38.76,7.19 38.76,8.08 ; U2.6 v1(7.01,22.81)
  TOP w0.889: 17.05,18.37 18.06,18.37 18.32,18.11 C22.2 ; 18.32,15.95 C22.2 ; 18.32,15.95 v1(18.32,14.05) ; 18.32,15.95 16.92,14.56 ; C22.2 17.16,16.96
  INNER_1 w0.508: 25.32,53.75 J1.7 ; J1.7 26.47,52.6 ; J1.7 27.63,53.75 ; J1.7 26.47,54.91 ; J16.2 77.42,16.91 ; J16.2 76.28,15.77 ; J16.2 77.42,14.62 ; J16.2 78.57,15.77 ; GND3.1 78.29,52.9 ; GND3.1 77.21,51.82 ; GND3.1 78.29,50.74 ; GND3.1 79.37,51.82 ; GND1.1 8.35,50.88 ; GND1.1 7.27,49.8 ; GND1.1 6.19,50.88 ; GND1.1 7.27,51.96 ; 78.82,15.77 J16.1 ; J16.1 79.96,14.62 ; J16.1 81.11,15.77 ; J16.1 79.96,16.91 ; J5.1 6.52,44.78 ; J5.1 5.12,43.38 ; J5.1 3.72,44.78 ; J5.1 5.12,46.18 ; 15.97,7.83 GND2.1 ; GND2.1 17.05,8.91 ; GND2.1 17.05,6.75 ; GND2.1 18.13,7.83 ; GND4.1 78.58,11 ; GND4.1 77.5,12.08 ; GND4.1 77.5,9.92 ; GND4.1 76.42,11 ; 43.12,4.42 J8.7 ; J8.7 42.04,5.5 ; J8.7 43.12,6.58 ; J8.7 44.2,5.5 ; 40.58,4.42 J8.6 ; J8.6 39.5,5.5 ; J8.6 40.58,6.58 ; J8.6 41.66,5.5
  INNER_2 w0.508: 39.5,5.5 J8.6 ; J8.6 40.58,4.42 ; J8.6 40.58,6.58 ; J8.6 41.66,5.5 ; 6.19,50.88 GND1.1 ; GND1.1 7.27,51.96 ; GND1.1 7.27,49.8 ; GND1.1 8.35,50.88 ; 15.97,7.83 GND2.1 ; GND2.1 18.13,7.83 ; GND2.1 17.05,8.91 ; GND2.1 17.05,6.75 ; 26.47,52.6 J1.7 ; J1.7 27.63,53.75 ; J1.7 26.47,54.91 ; J1.7 25.32,53.75 ; 5.12,43.38 J5.1 ; J5.1 5.12,46.18 ; J5.1 3.72,44.78 ; J5.1 6.52,44.78 ; 43.12,4.42 J8.7 ; J8.7 44.2,5.5 ; J8.7 43.12,6.58 ; J8.7 42.04,5.5 ; J16.2 78.57,15.77 ; J16.2 76.28,15.77 ; J16.2 77.42,16.91 ; GND4.1 80.67,11 v1(83.59,13.92) v1(83.59,20.78) v1(83.59,25.22) v1(83.59,29.8) v1(83.59,41.61) 83.59,46.52 GND3.1 ; GND4.1 76.42,11 ; GND4.1 77.5,9.92 ; GND4.1 77.5,12.08 ; J16.1 79.96,16.91 ; J16.1 81.11,15.77 ; J16.1 78.82,15.77 ; 77.21,51.82 GND3.1 ; GND3.1 79.37,51.82 ; GND3.1 78.29,52.9
  BOTTOM w0.508: J16.2 78.57,15.77 ; J16.2 77.42,16.91 ; J16.2 76.28,15.77 ; J16.2 77.42,14.62 ; 43.12,4.42 J8.7 ; J8.7 43.12,6.58 ; J8.7 44.2,5.5 ; J8.7 42.04,5.5 ; 78.82,15.77 J16.1 ; J16.1 81.11,15.77 ; J16.1 79.96,14.62 ; J16.1 79.96,16.91 ; 15.97,7.83 GND2.1 ; GND2.1 18.13,7.83 ; GND2.1 17.05,8.91 ; GND2.1 17.05,6.75 ; J8.6 41.66,5.5 ; J8.6 40.58,4.42 ; J8.6 39.5,5.5 ; J8.6 40.58,6.58 ; GND3.1 78.29,52.77 ; GND3.1 79.25,51.82 ; GND3.1 77.34,51.82 ; GND3.1 78.29,50.87 ; J1.7 27.63,53.75 ; J1.7 26.47,54.91 ; J1.7 25.32,53.75 ; J1.7 26.47,52.6 ; 76.42,11 GND4.1 ; GND4.1 77.5,9.92 ; GND4.1 78.58,11 ; GND4.1 77.5,12.08 ; 3.72,44.78 J5.1 ; J5.1 6.52,44.78 ; J5.1 5.12,46.18 ; J5.1 5.12,43.38 ; GND1.1 7.27,51.96 ; GND1.1 8.35,50.88 ; GND1.1 7.27,49.8 ; GND1.1 6.19,50.88
  vias: v1(1.17,15.95) v1(1.3,42.5) v1(1.42,33.73) v1(1.81,26.75) v1(1.81,21.92) v1(1.93,9.6) v1(2.95,48.85) v1(3.46,5.79) v1(4.85,48.34) v1(7.01,47.83) v1(7.01,2.62) v1(7.39,55.07) v1(9.55,53.16) v1(9.68,48.97) v1(9.68,21.8) v1(9.68,18.62) v1(11.08,19.26) v1(12.09,16.21) v1(12.22,1.09) v1(13.24,17.99) v1(13.49,21.67) v1(14.51,19.64) v1(14.89,51.39) v1(15.39,54.69) v1(15.52,15.19) v1(15.78,18.49) v1(16.92,1.09) v1(19.84,57.61) v1(22,44.66) v1(23.52,1.09) v1(26.06,14.3) v1(27.59,33.23) v1(27.71,44.34) v1(27.71,25.92) v1(27.84,22.11) v1(28.09,56.97) v1(28.22,36.78) v1(28.6,8.59) v1(28.98,47.7) v1(29.11,12.02) v1(29.75,45.67) v1(29.74,27.07) v1(30.38,32.34) v1(32.03,28.78) v1(32.16,38.18) v1(32.31,24.99) v1(32.41,34.5) v1(33.17,44.02) v1(33.41,22.28) v1(34.32,1.09) v1(34.44,56.59) v1(34.44,39.96) v1(34.7,31.96) v1(34.83,28.53) v1(37.11,46.69) v1(37.24,33.35) v1(37.37,17.73) v1(37.49,49.61) v1(37.75,38.81) v1(38.13,21.67) v1(38.51,27.51) v1(39.02,57.1) v1(39.4,1.09) v1(39.78,43.45) v1(41.05,46.56) v1(41.18,34.75) v1(42.06,25.61) v1(43.46,57.1) v1(43.72,39.19) v1(43.72,22.43) v1(44.35,43.45) v1(44.35,15.45) v1(44.72,29.17) v1(44.75,31.68) v1(44.76,30.41) v1(44.86,46.75) v1(45.87,44.4) v1(46.03,31.67) v1(46,30.44) v1(46,29.14) v1(47.2,31.68) v1(47.23,29.14) v1(47.24,30.4) v1(47.65,56.97) v1(47.91,18.49) v1(47.91,3.63) v1(48.17,39.9) v1(48.29,44.02) v1(48.29,21.16) v1(48.67,46.75) v1(48.8,37.29) v1(49.81,25.73) v1(49.94,34.24) v1(50.07,15.45) v1(50.57,43.13) v1(51.21,1.35) v1(51.72,18.49) v1(52.22,46.69) v1(52.48,26.49) v1(52.86,45.54) v1(52.99,36.78) v1(53.11,56.85) v1(53.37,32.72) v1(53.49,23.45) v1(54.76,43.13) v1(54.89,32.08) v1(54.89,20.91) v1(55.5,34.47) v1(55.65,40.21) v1(55.78,28.02) v1(56.29,23.32) v1(56.42,46.56) v1(57.05,26.88) v1(57.65,32.04) v1(57.69,28.65) v1(57.94,18.49) v1(58.07,43.13) v1(58.32,20.91) v1(58.83,37.92) v1(58.96,35.96) v1(60.1,26.75) v1(60.23,24.21) v1(60.23,2.36) v1(60.35,33.1) v1(60.73,44.4) v1(60.86,39.96) v1(60.9,37.2) v1(61.37,14.68) v1(62.64,47.32) v1(62.64,15.32) v1(64.42,41.1) v1(64.8,45.04) v1(64.8,38.05) v1(64.8,22.05) v1(65.94,41.86) v1(67.34,53.8) v1(67.46,41.61) v1(68.1,19.76) v1(68.23,1.98) v1(68.86,4.78) v1(69.75,8.21) v1(70.85,47.16) v1(71.91,4.78) v1(73.43,53.93) v1(73.43,11.51) v1(76.23,47.2) v1(76.35,54.94) v1(77.88,7.06) v1(80.42,11.89) v1(80.55,53.04)
AMUX: length 24.9
  TOP w0.508: 64.67,8.71 66.19,8.71 69.75,12.27 69.75,22.49 68.42,23.83 C23.1 65.76,23.83 R22.1 63.86,23.62 63.53,23.95 TP9.1
BATTERY: length 41.4
  TOP w0.508: 11.52,43.22 D4.C ; D4.C 12.98,41.81 ; D4.C 12.98,44.63 ; D4.C 14.44,43.22 ; 12.66,28.91 D1.A ; D1.A 14,30.65 ; D1.A 14,27.17 ; D1.A 15.33,28.91 ; J5.2 5.12,41.1 ; J5.2 6.52,39.7 ; J5.2 3.72,39.7 ; J5.2 5.12,38.3 ; 5.81,33.99 J4.1 ; J4.1 6.89,32.91 ; J4.1 6.89,35.07 ; J4.1 7.97,33.99 ; C42.1 13.99,37.42 ; C42.1 11.47,36.15 ; C42.1 16.5,36.15 ; C42.1 13.99,34.88 ; 19.08,41.54 BATT1.1 ; BATT1.1 20.16,42.62 ; BATT1.1 18,42.62 ; BATT1.1 19.08,43.7
  INNER_2 w0.508: BATT1.1 20.16,42.62 ; BATT1.1 19.08,43.7 ; BATT1.1 19.08,41.54 ; BATT1.1 18,42.62 ; J16.35 78.57,43.71 ; J16.35 77.42,44.85 ; J16.35 76.28,43.71
CS_B: length 21.5
  TOP w0.305: TP6.1 51.52,32.14 U3.32
  TOP w0.381: R37.1 TP6.1
CSB_M: length 36.2
  TOP w0.381: R37.2 v1(66.96,44.15)
  INNER_2 w0.381: v1(66.96,44.15) 62.26,48.85 40.27,48.85 36.63,52.48 J1.3
INT_B: length 53.5
  TOP w0.305: TP7.1 53.89,28.64 U3.25
  TOP w0.381: v1(64.29,28.4) 64.29,34.5 68.35,38.56 68.35,44.66 64.42,48.59 R41.1
  TOP w0.508: R23.1 TP7.1
  INNER_2 w0.381: v1(64.29,28.4) 64.29,23.32 62.38,21.41 TP7.1
INTB_M: length 3.7
  TOP w0.381: R41.2 63.53,50.88 63.51,50.9 J2.1
MISO: length 80.5
  TOP w0.305: U3.28 58.41,30.14 59.84,31.57 TP4.1
  TOP w0.381: v1(16.28,45.54) R48.2 R49.2 16.28,50.12 17.55,51.39 R39.1
  INNER_2 w0.381: v1(16.28,45.54) 23.14,45.54 27.08,41.61 49.18,41.61 59.21,31.57 TP4.1
MISO_M: length 5.7
  TOP w0.381: J1.5 30.33,52.53 29.11,52.53 27.97,51.39 R39.2
MOSI: length 60.3
  TOP w0.305: U3.30 54.97,31.14 59.21,35.38 TP5.1
  TOP w0.381: R40.1 R51.1 R50.1 v1(27.97,46.69)
  INNER_2 w0.381: v1(27.97,46.69) 27.97,46.43 31.52,42.88 49.81,42.88 57.3,35.38 TP5.1
MOSI_M: length 7.5
  TOP w0.381: R40.2 29.75,50.12 29.7,50.17 29.7,51.34 30.13,51.77 32.11,51.77 J1.4
SCLK: length 20.1
  TOP w0.305: TP3.1 61.11,39.19 53.56,31.64 U3.31
  TOP w0.381: R38.1 TP3.1
SCLK_M: length 45.4
  TOP w0.381: R38.2 66.96,39.96 66.58,40.34 v1(66.19,40.34)
  INNER_2 w0.381: J1.6 35.31,47.45 60.73,47.45 64.67,43.51 64.67,41.86 v1(66.19,40.34)
SG0: length 17.3
  TOP w0.305: U3.5 45.73,34.47 45.75,34.48 45.75,43.13 SG0.1
  TOP w0.381: R1.2 42.37,46.51 SG0.1
SG0R: length 65.5
  TOP w0.381: C1.1 44.12,50.6 ; 44.12,50.6 v1(45.24,50.6) ; 44.12,50.6 44.3,50.42 R1.1 ; v1(73.31,19.51) 78.76,19.51 J16.4
  BOTTOM w0.381: v1(73.31,19.51) 73.31,43.89 67.21,49.99 45.85,49.99 v1(45.24,50.6)
SG1: length 18.6
  TOP w0.305: SG1.1 45.23,39.84 U3.6
  TOP w0.381: SG1.1 38.56,46.51 R2.2
SG1R: length 66.3
  TOP w0.381: v1(41.43,50.62) C2.1 40.49,50.42 R2.1 ; v1(72.67,22.43) 73.11,21.99 78.82,21.99 J16.7
  BOTTOM w0.381: v1(72.67,22.43) 72.67,23 72.54,23.13 72.54,43.51 66.7,49.35 42.7,49.35 v1(41.43,50.62)
SG2: length 20
  TOP w0.305: SG2.1 44.73,36.53 44.73,33.53 44.73,33.53 U3.7
  TOP w0.381: R3.2 34.75,46.51 SG2.1
SG2R: length 67.5
  TOP w0.381: R3.1 36.68,50.42 C3.1 v1(37.62,50.62) ; J16.10 78.76,24.59 72.61,24.59 72.48,24.72 v1(71.91,24.72)
  BOTTOM w0.381: v1(71.91,24.72) 71.91,43 66.19,48.72 39.52,48.72 v1(37.62,50.62)
SG3: length 22.3
  TOP w0.305: SG3.1 33.43,45.54 44.23,34.74 U3.8
  TOP w0.381: SG3.1 30.94,46.51 R4.2
SG3R: length 68.6
  TOP w0.381: R4.1 32.67,48.92 C4.1 v1(33.81,50.62) ; J16.13 78.76,27.13 v1(71.21,27.13)
  BOTTOM w0.381: v1(71.21,27.13) 71.21,42.69 65.81,48.08 36.35,48.08 v1(33.81,50.62)
SG4: length 22.2
  TOP w0.305: SG4.1 40.23,32.14 U3.9
  TOP w0.381: SG4.1 28.4,42.04 R5.2
SG4R: length 66.6
  TOP w0.381: v1(67.68,31.04) 68.92,29.8 78.63,29.8 J16.16 ; v1(26.19,44.91) R5.1 24.49,43.97 C5.1
  BOTTOM w0.381: v1(26.19,44.91) 30,44.91 32.41,42.5 59.59,42.5 60.99,41.1 62.89,41.1 67.68,36.31 v1(67.68,31.04)
SG5: length 20.9
  TOP w0.305: SG5.1 36.92,31.64 U3.10
  TOP w0.381: R6.2 28.4,38.23 SG5.1
SG5R: length 63.1
  TOP w0.381: v1(66.96,32.21) 78.76,32.21 J16.19 ; v1(26.19,41.16) R6.1 24.49,40.16 C6.1
  BOTTOM w0.381: v1(26.19,41.16) 26.76,41.16 26.82,41.1 31.27,41.1 31.91,41.73 58.19,41.73 62.39,37.54 64.37,37.54 66.96,34.96 v1(66.96,32.21)
SG6: length 19.5
  TOP w0.305: SG6.1 33.61,31.14 U3.11
  TOP w0.381: R7.2 28.4,34.42 SG6.1
SG6R: length 61.2
  TOP w0.381: v1(65.94,34.88) 78.63,34.88 J16.22 ; v1(26.19,37.29) R7.1 24.49,36.35 C7.1
  BOTTOM w0.381: v1(65.94,34.88) 63.91,36.91 62,36.91 58.07,40.85 33.43,40.85 30.25,37.67 27.27,37.67 26.89,37.29 v1(26.19,37.29)
SG7: length 19.8
  TOP w0.305: SG7.1 34.42,29.64 U3.14
  TOP w0.381: R8.2 28.4,23.62 SG7.1
SG7R: length 77.2
  TOP w0.381: J16.25 78.76,37.29 v1(68.38,37.29) ; C8.1 24.49,25.55 R8.1 v1(26.19,26.49)
  BOTTOM w0.381: v1(26.19,26.49) 30,26.49 38.76,17.73 62.89,17.73 68.38,23.22 v1(68.38,37.29)
SG8: length 21.2
  TOP w0.305: U3.15 37.73,29.14 SG8.1
  TOP w0.381: R9.2 28.4,19.81 SG8.1
SG8R: length 79.1
  TOP w0.381: v1(69.12,39.83) 78.76,39.83 J16.28 ; v1(26.19,22.68) R9.1 24.49,21.74 C9.1
  BOTTOM w0.381: v1(69.12,39.83) 69.12,22.68 63.4,16.97 36.35,16.97 30.63,22.68 v1(26.19,22.68)
SG9: length 22.6
  TOP w0.305: U3.16 41.04,28.64 SG9.1
  TOP w0.381: SG9.1 28.4,16 R10.2
SG9R: length 80.8
  TOP w0.381: v1(26.19,18.87) R10.1 24.49,17.93 C10.1 ; J16.31 78.76,42.37 v1(69.88,42.37)
  BOTTOM w0.381: v1(26.19,18.87) 33.05,18.87 35.71,16.21 63.65,16.21 69.88,22.43 v1(69.88,42.37)
SG10: length 23.5
  TOP w0.305: SG10.1 44.23,25.49 U3.17
  TOP w0.381: SG10.1 30.94,12.19 R11.2
SG10R: length 75.5
  TOP w0.381: v1(33.81,9.98) R11.1 32.87,8.28 C11.1
  INNER_2 w0.381: v1(33.81,9.98) 35.59,11.76 64.92,11.76 66.32,13.16 66.32,28.02 70,31.7 70,37.04 73.31,40.34 73.31,41.41 74.27,42.37 78.63,42.37 J16.34
SG11: length 22.1
  TOP w0.305: U3.18 44.73,22.18 SG11.1
  TOP w0.381: R12.2 34.75,12.19 SG11.1
SG11R: length 67.6
  TOP w0.381: v1(37.62,9.98) R12.1 36.68,8.28 C12.1
  INNER_2 w0.381: v1(37.62,9.98) 38.76,11.13 65.56,11.13 68.73,14.3 68.73,29.29 71.02,31.57 71.02,36.91 74.07,39.96 76.22,39.96 J16.32
SG12: length 20.7
  TOP w0.305: U3.19 45.23,18.87 SG12.1
  TOP w0.381: R13.2 38.56,12.19 SG12.1
SG12R: length 61.8
  TOP w0.381: C13.1 40.49,8.28 R13.1 v1(41.43,9.98)
  INNER_2 w0.381: J16.29 76.22,37.42 74.2,37.42 71.91,35.13 71.91,31.45 69.37,28.91 69.37,13.79 66.13,10.56 42,10.56 v1(41.43,9.98)
SG13: length 19.3
  TOP w0.305: U3.20 45.73,15.56 SG13.1
  TOP w0.381: SG13.1 42.37,12.19 R14.2
SG13R: length 56.4
  TOP w0.381: v1(45.18,9.73) 45.11,9.73 44.86,9.98 R14.1 44.3,8.28 C14.1
  INNER_2 w0.381: J16.26 76.22,34.88 73.94,34.88 72.67,33.61 72.67,31.32 70,28.65 70,13.41 66.58,9.98 46.13,9.98 45.87,9.73 v1(45.18,9.73)
SP0: length 20.8
  TOP w0.305: U3.1 47.73,34.7 SP0.1
  TOP w0.381: SP0.1 57.61,46.51 R24.1
SP0R: length 67.1
  TOP w0.381: R24.2 59.54,50.42 C38.1 59.97,50.62 v1(60.73,51.39)
  INNER_2 w0.381: J16.3 76.22,14.43 81.43,14.43 82.96,15.95 82.96,45.42 77.13,51.25 76.98,51.25 76.84,51.39 v1(60.73,51.39)
SP1: length 19.4
  TOP w0.305: SP1.1 47.23,38.01 U3.2
  TOP w0.381: R25.1 53.8,46.51 SP1.1
SP1R: length 64.2
  TOP w0.381: R25.2 55.73,50.42 C37.1 56.16,50.62 v1(56.42,50.88)
  INNER_2 w0.381: v1(56.42,50.88) 57.11,50.88 57.24,50.75 76.74,50.75 82.32,45.16 82.32,20.65 81.18,19.51 76.09,19.51 J16.6
SP2: length 18
  TOP w0.305: SP2.1 46.73,41.32 U3.3
  TOP w0.381: R26.1 49.99,46.51 SP2.1
SP2R: length 64.4
  TOP w0.381: v1(52.73,50.56) 52.67,50.56 52.61,50.62 C36.1 51.92,50.42 R26.2
  INNER_2 w0.381: J16.9 76.09,22.05 81.43,22.05 81.82,22.43 81.82,44.66 76.4,50.07 53.23,50.07 v1(52.73,50.56)
SP3: length 16.7
  TOP w0.305: U3.4 46.23,41.97 47.14,42.88 SP3.1
  TOP w0.381: SP3.1 46.18,46.51 R27.1
SP3R: length 64.2
  TOP w0.381: v1(49.05,50.62) C35.1 48.11,50.42 R27.2
  INNER_2 w0.381: J16.12 76.09,24.59 80.8,24.59 81.18,24.97 81.18,44.27 75.97,49.48 50.19,49.48 v1(49.05,50.62)
SP4: length 18.7
  TOP w0.305: SP4.1 47.14,15.7 46.23,16.61 U3.21
  TOP w0.381: SP4.1 46.18,12.19 R28.1
SP4R: length 45
  TOP w0.381: v1(49.11,9.41) 49.11,9.48 49.18,9.54 49.18,9.6 48.8,9.98 R28.2 48.11,8.28 C34.1
  INNER_2 w0.381: v1(49.11,9.41) 51.84,6.68 67.08,6.68 72.67,12.27 72.67,20.53 73.43,21.29 73.43,24.48 J16.15
SP5: length 20.1
  TOP w0.305: SP5.1 46.73,17.38 U3.22
  TOP w0.381: SP5.1 49.99,12.19 R29.1
SP5R: length 42.7
  TOP w0.381: C33.1 51.92,8.28 R29.2 52.86,9.98 52.92,9.92 52.92,9.29 v1(52.99,9.22)
  INNER_2 w0.381: J16.18 72.93,26.51 72.93,24.59 72.04,23.7 72.04,12.65 66.83,7.44 54.76,7.44 v1(52.99,9.22)
SP6: length 21.5
  TOP w0.305: U3.23 47.23,20.69 SP6.1
  TOP w0.381: R30.1 53.8,12.19 SP6.1
SP6R: length 39.5
  TOP w0.381: C32.1 55.73,8.28 R30.2 56.16,9.98 56.73,9.41 v1(56.73,9.29)
  INNER_2 w0.381: J16.21 72.54,28.67 72.54,27.26 71.27,25.99 71.27,12.78 67.21,8.71 57.3,8.71 v1(56.73,9.29)
SP7: length 22.8
  TOP w0.305: SP7.1 47.73,24 U3.24
  TOP w0.381: R31.1 57.61,12.19 SP7.1
SP7R: length 37.1
  TOP w0.381: C31.1 59.54,8.28 R31.2 60.35,9.98 60.86,9.48 v1(60.86,9.41)
  INNER_2 w0.381: v1(60.86,9.41) 66.89,9.41 70.64,13.16 70.64,28.15 73.43,30.94 73.43,32.1 J16.24
WAKE_B: length 41.1
  TOP w0.305: U3.13 30.85,30.14 v1(28.48,27.76) R36.1
  TOP w0.381: R64.1 9.68,24.97 TP8.1
  INNER_2 w0.381: TP8.1 12.22,24.46 22.63,24.46 25.94,27.76 v1(28.48,27.76)
N46347: length 18.6
  TOP w0.305: R22.2 59.64,25.55 56.06,29.14 U3.26
N63980: length 11.8
  TOP w0.508: 20.44,7.95 20.44,7.98 19.08,9.34 J6.2
  INNER_2 w0.381: J6.2 20.22,12.52 24.79,12.52 J7.1
N64526: length 24.6
  TOP w0.381: v1(23.65,27.76) R36.2
  TOP w0.508: J7.2 25.05,7.95 D2.C
  BOTTOM w0.381: v1(23.65,27.76) 23.65,11.13 J7.2
N74267: length 5.6
  TOP w0.508: R23.2 66.91,18.07 D3.C 67.24,16.3 67.59,15.95 J3.2
N81888: length 3.1
  TOP w0.381: J4.2 4.35,32.91 3.94,32.5 D5.A
N159644: length 17.6
  TOP w1.016: 22,5.41 23.9,5.41 25.68,3.63 36.17,3.63 J8.5
N159652: length 25.6
  TOP w1.016: 22,3.76 23.21,3.76 24.73,2.24 42.4,2.24 J8.8
N165115: length 13.7
  TOP w0.381: J9.1 52.01,6.68 59.84,6.68 61.88,8.71 R47.2
N224295: length 4
  TOP w0.381: R62.1 R61.1 U2.4
N235544: length 5.3
  TOP w0.381: 8.28,24.45 8.28,25.73 7.9,26.11 R63.2 8.28,26.88 8.92,27.51 8.92,28.02 9.3,28.4 R64.2
N794881: length 2.3
  TOP w0.381: D5.C R44.2
N1652660: length 2.4
  TOP w0.381: J17.1 19.16,46.72 19.13,46.69 R48.1
N1652840: length 2.4
  TOP w0.381: R49.1 19.13,49.23 19.16,49.26 J17.3
N1653021: length 2.4
  TOP w0.381: J17.2 23.86,46.72 23.9,46.69 R50.2
N1653201: length 2.4
  TOP w0.381: J17.4 23.86,49.26 23.9,49.23 R51.2

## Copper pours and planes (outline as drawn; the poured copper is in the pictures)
3V3_MCU on TOP: 10.82,13.03 13.36,13.03 13.87,12.52 13.87,7.06 12.98,6.17 11.33,6.17 9.55,7.95 9.55,11.76
3V3_MCU on INNER_2: 10.7,8.97 12.98,8.97 14.12,7.83 14.12,6.68 15.65,5.16 33.81,5.16 34.06,5.41 34.06,6.81 34.57,7.32 36.6,7.32 36.98,6.94 36.98,3.25 35.71,1.98 12.73,1.98 9.81,4.9 9.81,8.08
5V0_MCU on TOP: 5.62,12.78 7.77,12.78 8.28,12.27 8.28,8.33 10.57,6.05 21.11,6.05 21.11,2.62 8.92,2.62 4.47,7.06 4.47,10.49 5.49,11.51 5.49,12.65
VBATP on TOP: 27.59,31.32 28.22,30.69 28.22,29.67 27.33,28.78 24.16,28.78 23.27,27.89 23.27,10.37 22.63,9.73 20.86,9.73 20.47,10.11 20.47,12.65 19.84,13.29 19.84,19.26 19.2,19.89 17.05,19.89 16.41,20.53 16.41,30.69 17.05,31.32
VBATP on TOP: 5.36,29.8 6.63,29.8 6.89,29.54 6.89,28.53 6.38,28.02 5.87,28.02 5.23,28.65 5.23,29.67
VBATP on INNER_2: 5.49,30.18 6.63,30.18 7.01,29.8 7.01,29.03 7.77,28.27 18.95,28.27 21.24,30.56 22.51,30.56 23.52,29.54 23.52,26.62 22,25.1 6.89,25.1 4.98,27 4.98,29.67
VDDQ on TOP: 2.82,13.16 4.73,13.16 5.11,12.78 5.11,11.51 4.6,11 3.08,11 2.57,11.51 2.57,12.91
VDDQ on INNER_2: 12.22,13.79 15.14,16.72 24.41,16.72 27.21,19.51 54.51,19.51 57.94,22.94 57.94,27.76 58.7,28.53 63.4,28.53 63.65,28.27 63.65,18.37 65.81,16.21 65.81,14.3 64.54,13.03 61.37,13.03 59.59,14.81 31.52,14.81 29.75,13.03 18.7,13.03 17.93,12.27 17.93,10.62 16.92,9.6 3.46,9.6 2.57,10.49 2.57,12.91 3.46,13.79
0 on TOP: 71.84,58.64 80.37,55.1 83.9,46.57 83.9,12.7 80.37,4.17 71.84,0.63 12.7,0.63 4.17,4.17 0.63,12.7 0.63,46.57 4.17,55.1 12.7,58.64 ; 50 cut-outs
0 on BOTTOM, INNER_1: 71.84,58.64 80.37,55.1 83.9,46.57 83.9,12.7 80.37,4.17 71.84,0.63 12.7,0.63 4.17,4.17 0.63,12.7 0.63,46.57 4.17,55.1 12.7,58.64
0 on INNER_2: 71.84,58.64 80.37,55.1 83.9,46.57 83.9,12.7 80.37,4.17 71.84,0.63 12.7,0.63 4.17,4.17 0.63,12.7 0.63,46.57 4.17,55.1 12.7,58.64 ; 26 cut-outs
BATTERY on TOP: 4.47,42.12 7.01,42.12 9.93,45.04 18.82,45.04 20.73,43.13 20.73,40.97 16.79,37.04 16.79,32.21 15.78,31.19 15.78,27.38 15.01,26.62 12.73,26.62 12.09,27.26 12.09,31.32 10.95,32.46 5.87,32.46 5.49,32.84 5.49,35.38 3.33,37.54 3.33,40.97
BATTERY on INNER_2: 17.3,44.27 19.84,44.27 22.76,41.35 48.16,41.35 58.96,30.56 62.89,30.56 63.91,31.57 63.91,35.89 71.15,43.13 71.15,44.78 72.54,46.18 76.99,46.18 78.64,44.53 78.64,43.13 78.26,42.75 74.2,42.75 72.93,41.48 72.93,40.59 69.37,37.04 69.37,31.83 66.45,28.91 55.02,28.91 45.62,38.31 19.46,38.31 16.66,41.1 16.66,43.64
OUT on TOP: 3.2,20.14 4.47,20.14 4.73,19.89 4.73,15.7 5.23,15.19 7.39,15.19 7.9,15.7 8.54,15.7 8.92,15.32 8.92,14.43 8.28,13.79 3.2,13.79 2.44,14.56 2.44,19.38
N222829 on TOP: 3.96,27.26 6.76,27.26 6.76,25.99 6.38,25.61 4.98,25.61 4.73,25.35 4.73,23.7 4.6,23.57 3.84,23.57 3.71,23.7 3.71,27

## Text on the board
BOTTOM: 170-29953 REV A | 4 OF 10 | SECONDARY SIDE
Board Geometry/Soldermask Bottom: 8 OF 10 | SECONDARY SOLDERMASK
Ref Des/Silkscreen Bottom: 10 of 10 | SECONDARY SILKSCREEN
User.Comments: 1 OF 1 | TEST PROBE | 1/1 | 1
TOP: 1 OF 10 | PRIMARY SIDE
Board Geometry/Soldermask Top: 5 OF 10 | PRIMARY SOLDERMASK
Ref Des/Silkscreen Top: GND | BATT | 7 OF 10 | FRDMCD1020EVM | PRIMARY SILKSCREEN
INNER_1: 2 of 10 | INNER LAYER 1
INNER_2: 3 of 10 | INNER LAYER 2
DIMENSION: GRID ORIGIN | PRIMARY DATUM
BODY_CENTER: 21. BASIC GRID INCREMENT AT 1.1 IS .0001, | 16 | 21 | 8
PASTEMASK_TOP: 6 OF 10 | PASTEMASK TOP
User.5: 9 OF 10 | SECONDARY PASTEMASK
User.20: FIGURE | SIZE | 10.0 | 40.0 | 41.0 | 51.0 | DRILL CHART: TOP to BOTTOM | ALL UNITS ARE IN MILS | TOLERANCE | +0.0/-10.0 | +3.0/-3.0 | PLATED | QTY | 242 | 116 | 6 | 2
